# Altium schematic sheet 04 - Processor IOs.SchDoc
size B; CompanyName: Microchip Technology Inc.; Organization: Microchip Technology; Address1: 2355 West Chandler Blvd.; Address2: Chandler, AZ  85224; Address4: USA; DocumentNumber: 4; SheetNumber: 4; SheetTotal: 13; SheetTitle: Processor IOs
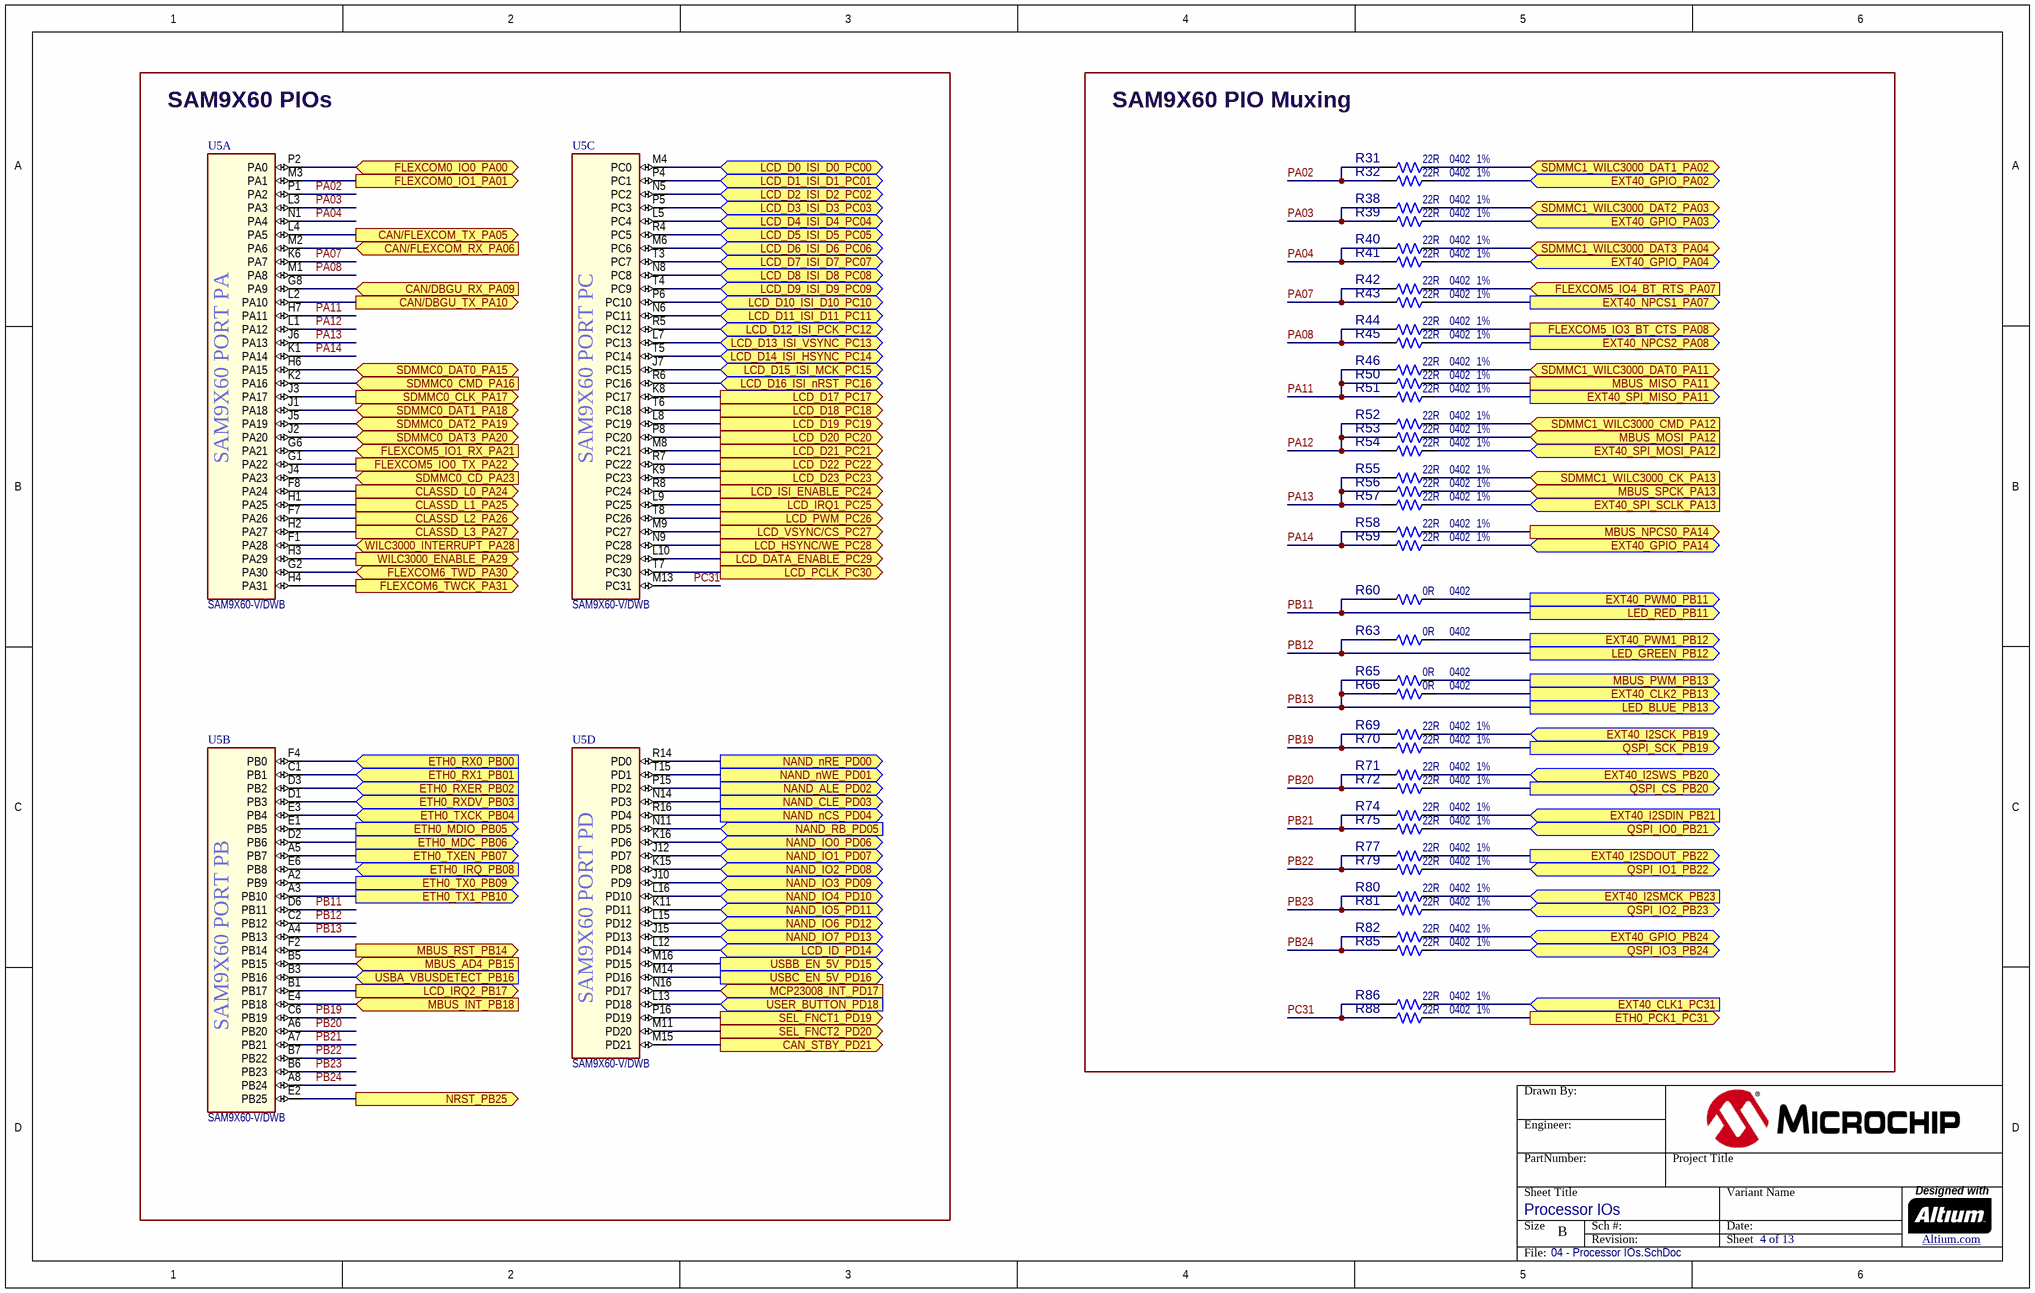
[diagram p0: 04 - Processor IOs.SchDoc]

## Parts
?  (no value)  (graphical)
R31  value 22R  Package: 0402  Tolerance: 1%  [RES_C_0402]  (hidden comment: Resistor)
R32  value 22R  Package: 0402  Tolerance: 1%  [RES_C_0402]  (hidden comment: Resistor)
R38  value 22R  Package: 0402  Tolerance: 1%  [RES_C_0402]  (hidden comment: Resistor)
R39  value 22R  Package: 0402  Tolerance: 1%  [RES_C_0402]  (hidden comment: Resistor)
R40  value 22R  Package: 0402  Tolerance: 1%  [RES_C_0402]  (hidden comment: Resistor)
R41  value 22R  Package: 0402  Tolerance: 1%  [RES_C_0402]  (hidden comment: Resistor)
R42  value 22R  Package: 0402  Tolerance: 1%  [RES_C_0402]  (hidden comment: Resistor)
R43  value 22R  Package: 0402  Tolerance: 1%  [RES_C_0402]  (hidden comment: Resistor)
R44  value 22R  Package: 0402  Tolerance: 1%  [RES_C_0402]  (hidden comment: Resistor)
R45  value 22R  Package: 0402  Tolerance: 1%  [RES_C_0402]  (hidden comment: Resistor)
R46  value 22R  Package: 0402  Tolerance: 1%  [RES_C_0402]  (hidden comment: Resistor)
R50  value 22R  Package: 0402  Tolerance: 1%  [RES_C_0402]  (hidden comment: Resistor)
R51  value 22R  Package: 0402  Tolerance: 1%  [RES_C_0402]  (hidden comment: Resistor)
R52  value 22R  Package: 0402  Tolerance: 1%  [RES_C_0402]  (hidden comment: Resistor)
R53  value 22R  Package: 0402  Tolerance: 1%  [RES_C_0402]  (hidden comment: Resistor)
R54  value 22R  Package: 0402  Tolerance: 1%  [RES_C_0402]  (hidden comment: Resistor)
R55  value 22R  Package: 0402  Tolerance: 1%  [RES_C_0402]  (hidden comment: Resistor)
R56  value 22R  Package: 0402  Tolerance: 1%  [RES_C_0402]  (hidden comment: Resistor)
R57  value 22R  Package: 0402  Tolerance: 1%  [RES_C_0402]  (hidden comment: Resistor)
R58  value 22R  Package: 0402  Tolerance: 1%  [RES_C_0402]  (hidden comment: Resistor)
R59  value 22R  Package: 0402  Tolerance: 1%  [RES_C_0402]  (hidden comment: Resistor)
R60  value 0R  Package: 0402  [RES_C_0402]  (hidden comment: Resistor)
R63  value 0R  Package: 0402  [RES_C_0402]  (hidden comment: Resistor)
R65  value 0R  Package: 0402  [RES_C_0402]  (hidden comment: Resistor)
R66  value 0R  Package: 0402  [RES_C_0402]  (hidden comment: Resistor)
R69  value 22R  Package: 0402  Tolerance: 1%  [RES_C_0402]  (hidden comment: Resistor)
R70  value 22R  Package: 0402  Tolerance: 1%  [RES_C_0402]  (hidden comment: Resistor)
R71  value 22R  Package: 0402  Tolerance: 1%  [RES_C_0402]  (hidden comment: Resistor)
R72  value 22R  Package: 0402  Tolerance: 1%  [RES_C_0402]  (hidden comment: Resistor)
R74  value 22R  Package: 0402  Tolerance: 1%  [RES_C_0402]  (hidden comment: Resistor)
R75  value 22R  Package: 0402  Tolerance: 1%  [RES_C_0402]  (hidden comment: Resistor)
R77  value 22R  Package: 0402  Tolerance: 1%  [RES_C_0402]  (hidden comment: Resistor)
R79  value 22R  Package: 0402  Tolerance: 1%  [RES_C_0402]  (hidden comment: Resistor)
R80  value 22R  Package: 0402  Tolerance: 1%  [RES_C_0402]  (hidden comment: Resistor)
R81  value 22R  Package: 0402  Tolerance: 1%  [RES_C_0402]  (hidden comment: Resistor)
R82  value 22R  Package: 0402  Tolerance: 1%  [RES_C_0402]  (hidden comment: Resistor)
R85  value 22R  Package: 0402  Tolerance: 1%  [RES_C_0402]  (hidden comment: Resistor)
R86  value 22R  Package: 0402  Tolerance: 1%  [RES_C_0402]  (hidden comment: Resistor)
R88  value 22R  Package: 0402  Tolerance: 1%  [RES_C_0402]  (hidden comment: Resistor)
U5  value SAM9X60-V/DWB  [SAM9X60 TFBGA-228]  (hidden comment: SAM9X60 TFBGA-228)  (parts A,B,C,D of 7)

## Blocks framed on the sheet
SAM9X60 PIOs: U5
SAM9X60 PIO Muxing: R31 R32 R38-R46 R50-R60 R63 R65 R66 R69-R72 R74 R75 R77 R79-R82 R85 R86 R88

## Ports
CAN/DBGU_RX_PA09 (in), CAN/DBGU_TX_PA10 (out), CAN/FLEXCOM_RX_PA06 (in), CAN/FLEXCOM_TX_PA05 (out), CAN_STBY_PD21 (out), CLASSD_L0_PA24 (out), CLASSD_L1_PA25 (out), CLASSD_L2_PA26 (out), CLASSD_L3_PA27 (out), ETH0_IRQ_PB08 (in), ETH0_MDC_PB06 (out), ETH0_MDIO_PB05 (out), ETH0_PCK1_PC31 (out), ETH0_RX0_PB00 (in), ETH0_RX1_PB01 (in), ETH0_RXDV_PB03 (in), ETH0_RXER_PB02 (in), ETH0_TX0_PB09 (out), ETH0_TX1_PB10 (out), ETH0_TXCK_PB04 (in), ETH0_TXEN_PB07 (out), EXT40_CLK1_PC31 (in), EXT40_CLK2_PB13 (out), EXT40_GPIO_PA02 (bidir), EXT40_GPIO_PA03 (bidir), EXT40_GPIO_PA04 (bidir), EXT40_GPIO_PA14 (bidir), EXT40_GPIO_PB24 (bidir), EXT40_I2SCK_PB19 (bidir), EXT40_I2SDIN_PB21 (in), EXT40_I2SDOUT_PB22 (out), EXT40_I2SMCK_PB23 (in), EXT40_I2SWS_PB20 (bidir), EXT40_NPCS1_PA07 (out), EXT40_NPCS2_PA08 (out), EXT40_PWM0_PB11 (out), EXT40_PWM1_PB12 (out), EXT40_SPI_MISO_PA11 (out), EXT40_SPI_MOSI_PA12 (in), EXT40_SPI_SCLK_PA13 (in), FLEXCOM0_IO0_PA00 (bidir), FLEXCOM0_IO1_PA01 (out), FLEXCOM5_IO0_TX_PA22 (out), FLEXCOM5_IO1_RX_PA21 (in), FLEXCOM5_IO3_BT_CTS_PA08 (out), FLEXCOM5_IO4_BT_RTS_PA07 (in), FLEXCOM6_TWCK_PA31 (out), FLEXCOM6_TWD_PA30 (bidir), LCD_D0_ISI_D0_PC00 (bidir), LCD_D1_ISI_D1_PC01 (bidir), LCD_D2_ISI_D2_PC02 (bidir), LCD_D3_ISI_D3_PC03 (bidir), LCD_D4_ISI_D4_PC04 (bidir), LCD_D5_ISI_D5_PC05 (bidir), LCD_D6_ISI_D6_PC06 (bidir), LCD_D7_ISI_D7_PC07 (bidir), LCD_D8_ISI_D8_PC08 (bidir), LCD_D9_ISI_D9_PC09 (bidir), LCD_D10_ISI_D10_PC10 (bidir), LCD_D11_ISI_D11_PC11 (bidir), LCD_D12_ISI_PCK_PC12 (bidir), LCD_D13_ISI_VSYNC_PC13 (bidir), LCD_D14_ISI_HSYNC_PC14 (bidir), LCD_D15_ISI_MCK_PC15 (bidir), LCD_D16_ISI_nRST_PC16 (bidir), LCD_D17_PC17 (out), LCD_D18_PC18 (out), LCD_D19_PC19 (out), LCD_D20_PC20 (out), LCD_D21_PC21 (out), LCD_D22_PC22 (out), LCD_D23_PC23 (out), LCD_DATA_ENABLE_PC29 (out), LCD_HSYNC/WE_PC28 (out), LCD_ID_PD14 (bidir), LCD_IRQ1_PC25 (out), LCD_IRQ2_PB17 (out), LCD_ISI_ENABLE_PC24 (out), LCD_PCLK_PC30 (out), LCD_PWM_PC26 (out), LCD_VSYNC/CS_PC27 (out), LED_BLUE_PB13 (out), LED_GREEN_PB12 (out), LED_RED_PB11 (out), MBUS_AD4_PB15 (in), MBUS_INT_PB18 (in), MBUS_MISO_PA11 (out), MBUS_MOSI_PA12 (in), MBUS_NPCS0_PA14 (out), MBUS_PWM_PB13 (out), MBUS_RST_PB14 (out), MBUS_SPCK_PA13 (in), MCP23008_INT_PD17 (in), NAND_ALE_PD02 (out), NAND_CLE_PD03 (out), NAND_IO0_PD06 (bidir), NAND_IO1_PD07 (bidir), NAND_IO2_PD08 (bidir), NAND_IO3_PD09 (bidir), NAND_IO4_PD10 (bidir), NAND_IO5_PD11 (bidir), NAND_IO6_PD12 (bidir), NAND_IO7_PD13 (bidir), NAND_nCS_PD04 (out), NAND_nRE_PD00 (out), NAND_nWE_PD01 (out), NAND_RB_PD05 (in), NRST_PB25 (out), QSPI_CS_PB20 (out), QSPI_IO0_PB21 (bidir), QSPI_IO1_PB22 (bidir), QSPI_IO2_PB23 (bidir), QSPI_IO3_PB24 (bidir), QSPI_SCK_PB19 (out), SDMMC0_CD_PA23 (in), SDMMC0_CLK_PA17 (out), SDMMC0_CMD_PA16 (in), SDMMC0_DAT0_PA15 (bidir), SDMMC0_DAT1_PA18 (bidir), SDMMC0_DAT2_PA19 (bidir), SDMMC0_DAT3_PA20 (bidir), SDMMC1_WILC3000_CK_PA13 (in), SDMMC1_WILC3000_CMD_PA12 (in), SDMMC1_WILC3000_DAT0_PA11 (bidir), SDMMC1_WILC3000_DAT1_PA02 (bidir), SDMMC1_WILC3000_DAT2_PA03 (bidir), SDMMC1_WILC3000_DAT3_PA04 (bidir), SEL_FNCT1_PD19 (out), SEL_FNCT2_PD20 (out), USBA_VBUSDETECT_PB16 (in), USBB_EN_5V_PD15 (out), USBC_EN_5V_PD16 (out), USER_BUTTON_PD18 (in), WILC3000_ENABLE_PA29 (out), WILC3000_INTERRUPT_PA28 (in)

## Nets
CAN/DBGU_RX_PA09: U5.G8(PA9) ; port CAN/DBGU_RX_PA09
CAN/DBGU_TX_PA10: U5.L2(PA10) ; port CAN/DBGU_TX_PA10
CAN/FLEXCOM_RX_PA06: U5.M2(PA6) ; port CAN/FLEXCOM_RX_PA06
CAN/FLEXCOM_TX_PA05: U5.L4(PA5) ; port CAN/FLEXCOM_TX_PA05
CAN_STBY_PD21: U5.M15(PD21) ; port CAN_STBY_PD21
CLASSD_L0_PA24: U5.F8(PA24) ; port CLASSD_L0_PA24
CLASSD_L1_PA25: U5.H1(PA25) ; port CLASSD_L1_PA25
CLASSD_L2_PA26: U5.F7(PA26) ; port CLASSD_L2_PA26
CLASSD_L3_PA27: U5.H2(PA27) ; port CLASSD_L3_PA27
ETH0_IRQ_PB08: U5.E6(PB8) ; port ETH0_IRQ_PB08
ETH0_MDC_PB06: U5.D2(PB6) ; port ETH0_MDC_PB06
ETH0_MDIO_PB05: U5.E1(PB5) ; port ETH0_MDIO_PB05
ETH0_PCK1_PC31: R88.1 ; port ETH0_PCK1_PC31
ETH0_RX0_PB00: U5.F4(PB0) ; port ETH0_RX0_PB00
ETH0_RX1_PB01: U5.C1(PB1) ; port ETH0_RX1_PB01
ETH0_RXDV_PB03: U5.D1(PB3) ; port ETH0_RXDV_PB03
ETH0_RXER_PB02: U5.D3(PB2) ; port ETH0_RXER_PB02
ETH0_TX0_PB09: U5.A2(PB9) ; port ETH0_TX0_PB09
ETH0_TX1_PB10: U5.A3(PB10) ; port ETH0_TX1_PB10
ETH0_TXCK_PB04: U5.E3(PB4) ; port ETH0_TXCK_PB04
ETH0_TXEN_PB07: U5.A5(PB7) ; port ETH0_TXEN_PB07
EXT40_CLK1_PC31: R86.1 ; port EXT40_CLK1_PC31
EXT40_CLK2_PB13: R66.2 ; port EXT40_CLK2_PB13
EXT40_GPIO_PA02: R32.1 ; port EXT40_GPIO_PA02
EXT40_GPIO_PA03: R39.1 ; port EXT40_GPIO_PA03
EXT40_GPIO_PA04: R41.1 ; port EXT40_GPIO_PA04
EXT40_GPIO_PA14: R59.1 ; port EXT40_GPIO_PA14
EXT40_GPIO_PB24: R82.1 ; port EXT40_GPIO_PB24
EXT40_I2SCK_PB19: R69.1 ; port EXT40_I2SCK_PB19
EXT40_I2SDIN_PB21: R74.1 ; port EXT40_I2SDIN_PB21
EXT40_I2SDOUT_PB22: R77.1 ; port EXT40_I2SDOUT_PB22
EXT40_I2SMCK_PB23: R80.1 ; port EXT40_I2SMCK_PB23
EXT40_I2SWS_PB20: R71.1 ; port EXT40_I2SWS_PB20
EXT40_NPCS1_PA07: R43.1 ; port EXT40_NPCS1_PA07
EXT40_NPCS2_PA08: R45.1 ; port EXT40_NPCS2_PA08
EXT40_PWM0_PB11: R60.2 ; port EXT40_PWM0_PB11
EXT40_PWM1_PB12: R63.2 ; port EXT40_PWM1_PB12
EXT40_SPI_MISO_PA11: R51.1 ; port EXT40_SPI_MISO_PA11
EXT40_SPI_MOSI_PA12: R54.1 ; port EXT40_SPI_MOSI_PA12
EXT40_SPI_SCLK_PA13: R57.1 ; port EXT40_SPI_SCLK_PA13
FLEXCOM0_IO0_PA00: U5.P2(PA0) ; port FLEXCOM0_IO0_PA00
FLEXCOM0_IO1_PA01: U5.M3(PA1) ; port FLEXCOM0_IO1_PA01
FLEXCOM5_IO0_TX_PA22: U5.G1(PA22) ; port FLEXCOM5_IO0_TX_PA22
FLEXCOM5_IO1_RX_PA21: U5.G6(PA21) ; port FLEXCOM5_IO1_RX_PA21
FLEXCOM5_IO3_BT_CTS_PA08: R44.1 ; port FLEXCOM5_IO3_BT_CTS_PA08
FLEXCOM5_IO4_BT_RTS_PA07: R42.1 ; port FLEXCOM5_IO4_BT_RTS_PA07
FLEXCOM6_TWCK_PA31: U5.H4(PA31) ; port FLEXCOM6_TWCK_PA31
FLEXCOM6_TWD_PA30: U5.G2(PA30) ; port FLEXCOM6_TWD_PA30
LCD_D0_ISI_D0_PC00: U5.M4(PC0) ; port LCD_D0_ISI_D0_PC00
LCD_D1_ISI_D1_PC01: U5.P4(PC1) ; port LCD_D1_ISI_D1_PC01
LCD_D2_ISI_D2_PC02: U5.N5(PC2) ; port LCD_D2_ISI_D2_PC02
LCD_D3_ISI_D3_PC03: U5.P5(PC3) ; port LCD_D3_ISI_D3_PC03
LCD_D4_ISI_D4_PC04: U5.L5(PC4) ; port LCD_D4_ISI_D4_PC04
LCD_D5_ISI_D5_PC05: U5.R4(PC5) ; port LCD_D5_ISI_D5_PC05
LCD_D6_ISI_D6_PC06: U5.M6(PC6) ; port LCD_D6_ISI_D6_PC06
LCD_D7_ISI_D7_PC07: U5.T3(PC7) ; port LCD_D7_ISI_D7_PC07
LCD_D8_ISI_D8_PC08: U5.N8(PC8) ; port LCD_D8_ISI_D8_PC08
LCD_D9_ISI_D9_PC09: U5.T4(PC9) ; port LCD_D9_ISI_D9_PC09
LCD_D10_ISI_D10_PC10: U5.P6(PC10) ; port LCD_D10_ISI_D10_PC10
LCD_D11_ISI_D11_PC11: U5.N6(PC11) ; port LCD_D11_ISI_D11_PC11
LCD_D12_ISI_PCK_PC12: U5.R5(PC12) ; port LCD_D12_ISI_PCK_PC12
LCD_D13_ISI_VSYNC_PC13: U5.L7(PC13) ; port LCD_D13_ISI_VSYNC_PC13
LCD_D14_ISI_HSYNC_PC14: U5.T5(PC14) ; port LCD_D14_ISI_HSYNC_PC14
LCD_D15_ISI_MCK_PC15: U5.J7(PC15) ; port LCD_D15_ISI_MCK_PC15
LCD_D16_ISI_nRST_PC16: U5.R6(PC16) ; port LCD_D16_ISI_nRST_PC16
LCD_D17_PC17: U5.K8(PC17) ; port LCD_D17_PC17
LCD_D18_PC18: U5.T6(PC18) ; port LCD_D18_PC18
LCD_D19_PC19: U5.L8(PC19) ; port LCD_D19_PC19
LCD_D20_PC20: U5.P8(PC20) ; port LCD_D20_PC20
LCD_D21_PC21: U5.M8(PC21) ; port LCD_D21_PC21
LCD_D22_PC22: U5.R7(PC22) ; port LCD_D22_PC22
LCD_D23_PC23: U5.K9(PC23) ; port LCD_D23_PC23
LCD_DATA_ENABLE_PC29: U5.L10(PC29) ; port LCD_DATA_ENABLE_PC29
LCD_HSYNC/WE_PC28: U5.N9(PC28) ; port LCD_HSYNC/WE_PC28
LCD_ID_PD14: U5.L12(PD14) ; port LCD_ID_PD14
LCD_IRQ1_PC25: U5.L9(PC25) ; port LCD_IRQ1_PC25
LCD_IRQ2_PB17: U5.B1(PB17) ; port LCD_IRQ2_PB17
LCD_ISI_ENABLE_PC24: U5.R8(PC24) ; port LCD_ISI_ENABLE_PC24
LCD_PCLK_PC30: U5.T7(PC30) ; port LCD_PCLK_PC30
LCD_PWM_PC26: U5.T8(PC26) ; port LCD_PWM_PC26
LCD_VSYNC/CS_PC27: U5.M9(PC27) ; port LCD_VSYNC/CS_PC27
MBUS_AD4_PB15: U5.B5(PB15) ; port MBUS_AD4_PB15
MBUS_INT_PB18: U5.E4(PB18) ; port MBUS_INT_PB18
MBUS_MISO_PA11: R50.1 ; port MBUS_MISO_PA11
MBUS_MOSI_PA12: R53.1 ; port MBUS_MOSI_PA12
MBUS_NPCS0_PA14: R58.1 ; port MBUS_NPCS0_PA14
MBUS_PWM_PB13: R65.2 ; port MBUS_PWM_PB13
MBUS_RST_PB14: U5.F2(PB14) ; port MBUS_RST_PB14
MBUS_SPCK_PA13: R56.1 ; port MBUS_SPCK_PA13
MCP23008_INT_PD17: U5.N16(PD17) ; port MCP23008_INT_PD17
NAND_ALE_PD02: U5.P15(PD2) ; port NAND_ALE_PD02
NAND_CLE_PD03: U5.N14(PD3) ; port NAND_CLE_PD03
NAND_IO0_PD06: U5.K16(PD6) ; port NAND_IO0_PD06
NAND_IO1_PD07: U5.J12(PD7) ; port NAND_IO1_PD07
NAND_IO2_PD08: U5.K15(PD8) ; port NAND_IO2_PD08
NAND_IO3_PD09: U5.J10(PD9) ; port NAND_IO3_PD09
NAND_IO4_PD10: U5.L16(PD10) ; port NAND_IO4_PD10
NAND_IO5_PD11: U5.K11(PD11) ; port NAND_IO5_PD11
NAND_IO6_PD12: U5.L15(PD12) ; port NAND_IO6_PD12
NAND_IO7_PD13: U5.J15(PD13) ; port NAND_IO7_PD13
NAND_nCS_PD04: U5.R16(PD4) ; port NAND_nCS_PD04
NAND_nRE_PD00: U5.R14(PD0) ; port NAND_nRE_PD00
NAND_nWE_PD01: U5.T15(PD1) ; port NAND_nWE_PD01
NAND_RB_PD05: U5.N11(PD5) ; port NAND_RB_PD05
NRST_PB25: U5.E2(PB25) ; port NRST_PB25
PA02: R31.2 R32.2 U5.P1(PA2)
PA03: R38.2 R39.2 U5.L3(PA3)
PA04: R40.2 R41.2 U5.N1(PA4)
PA07: R42.2 R43.2 U5.K6(PA7)
PA08: R44.2 R45.2 U5.M1(PA8)
PA11: R46.2 R50.2 R51.2 U5.H7(PA11)
PA12: R52.2 R53.2 R54.2 U5.L1(PA12)
PA13: R55.2 R56.2 R57.2 U5.J6(PA13)
PA14: R58.2 R59.2 U5.K1(PA14)
PB11: R60.1 U5.D6(PB11) ; port LED_RED_PB11
PB12: R63.1 U5.C2(PB12) ; port LED_GREEN_PB12
PB13: R65.1 R66.1 U5.A4(PB13) ; port LED_BLUE_PB13
PB19: R69.2 R70.2 U5.C6(PB19)
PB20: R71.2 R72.2 U5.A6(PB20)
PB21: R74.2 R75.2 U5.A7(PB21)
PB22: R77.2 R79.2 U5.B7(PB22)
PB23: R80.2 R81.2 U5.B6(PB23)
PB24: R82.2 R85.2 U5.A8(PB24)
PC31: R86.2 R88.2 U5.M13(PC31)
QSPI_CS_PB20: R72.1 ; port QSPI_CS_PB20
QSPI_IO0_PB21: R75.1 ; port QSPI_IO0_PB21
QSPI_IO1_PB22: R79.1 ; port QSPI_IO1_PB22
QSPI_IO2_PB23: R81.1 ; port QSPI_IO2_PB23
QSPI_IO3_PB24: R85.1 ; port QSPI_IO3_PB24
QSPI_SCK_PB19: R70.1 ; port QSPI_SCK_PB19
SDMMC0_CD_PA23: U5.J4(PA23) ; port SDMMC0_CD_PA23
SDMMC0_CLK_PA17: U5.J3(PA17) ; port SDMMC0_CLK_PA17
SDMMC0_CMD_PA16: U5.K2(PA16) ; port SDMMC0_CMD_PA16
SDMMC0_DAT0_PA15: U5.H6(PA15) ; port SDMMC0_DAT0_PA15
SDMMC0_DAT1_PA18: U5.J1(PA18) ; port SDMMC0_DAT1_PA18
SDMMC0_DAT2_PA19: U5.J5(PA19) ; port SDMMC0_DAT2_PA19
SDMMC0_DAT3_PA20: U5.J2(PA20) ; port SDMMC0_DAT3_PA20
SDMMC1_WILC3000_CK_PA13: R55.1 ; port SDMMC1_WILC3000_CK_PA13
SDMMC1_WILC3000_CMD_PA12: R52.1 ; port SDMMC1_WILC3000_CMD_PA12
SDMMC1_WILC3000_DAT0_PA11: R46.1 ; port SDMMC1_WILC3000_DAT0_PA11
SDMMC1_WILC3000_DAT1_PA02: R31.1 ; port SDMMC1_WILC3000_DAT1_PA02
SDMMC1_WILC3000_DAT2_PA03: R38.1 ; port SDMMC1_WILC3000_DAT2_PA03
SDMMC1_WILC3000_DAT3_PA04: R40.1 ; port SDMMC1_WILC3000_DAT3_PA04
SEL_FNCT1_PD19: U5.P16(PD19) ; port SEL_FNCT1_PD19
SEL_FNCT2_PD20: U5.M11(PD20) ; port SEL_FNCT2_PD20
USBA_VBUSDETECT_PB16: U5.B3(PB16) ; port USBA_VBUSDETECT_PB16
USBB_EN_5V_PD15: U5.M16(PD15) ; port USBB_EN_5V_PD15
USBC_EN_5V_PD16: U5.M14(PD16) ; port USBC_EN_5V_PD16
USER_BUTTON_PD18: U5.L13(PD18) ; port USER_BUTTON_PD18
WILC3000_ENABLE_PA29: U5.H3(PA29) ; port WILC3000_ENABLE_PA29
WILC3000_INTERRUPT_PA28: U5.F1(PA28) ; port WILC3000_INTERRUPT_PA28

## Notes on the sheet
- (near U5) SAM9X60 PORT PA
- (near U5) SAM9X60 PORT PC
- (near U5) SAM9X60 PORT PB
- (near U5) SAM9X60 PORT PD

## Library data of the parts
? = Title Block B
R31 R32 R38-R46 R50-R59 R69-R72 R74 R75 R77 R79-R82 R85 R86 R88 = RES1474: Manufacturer 1: Panasonic Electronic Components; Manufacturer Part Number 1: ERJ-2RKF22R0X; Description_: RES TKF 22R 1% 1/20W SMD 0402; Dev Tools Status: Production; Temperature Coeffcient: 100ppm/C; Circuit Type: Isolated; Power: 1/10W; Owner: Mike Ragsdale; Populated: YES
R60 R63 R65 R66 = RSMT1040: Manufacturer 1: Yageo; Manufacturer Part Number 1: RC0402JR-070RL; Description_: RES TKF 0R 1/16W SMD 0402; Dev Tools Status: Production; Power: 1/16W; Owner: Sompoch Loboonlert; Populated: Yes
U5 = MIC8772: SAM9X60 MPU 600MHz ARM926EJ-S TFBGA-228; Manufacturer 1: Microchip; Description_: MCHP MCU 32-BIT 600 MHz 64kB  SAM9X60-V/DWB TFBGA228; Populated: YES; MAPS Description: ARM926 MPU, BGA, IND TEMP; Dev Tools Status: Design; Owner: Ilie Galan; MPC: STU029DWBR01; LeadContent: Pb-FREE; TempRange: Various; Stage: NREL; PackageWidth: 11x11x1.2mm; PackingMedia: TRAY; ForceMinOrderQtyMult: True; MinOrderQty: 176; LeadCount: 228; Program Memory KBytes: 0; Ram: 69584; IOPins: 112; MaxSpeed: 600; OscillatorMHz: 32kHz, 12MHz; ADC Channels: 12; USART: 13; SPI: 6; CAN: 2; USBChannels: 3; DigitalTimerQty_32bit: 8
